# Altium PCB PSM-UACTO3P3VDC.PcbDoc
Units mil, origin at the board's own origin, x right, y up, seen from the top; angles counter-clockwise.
Board outline 8000 x 5800 mil, 2 copper layers (Top Layer, Bottom Layer), stack 62 mil thick; 68 components, 35 nets, 165 pads, 15 vias.
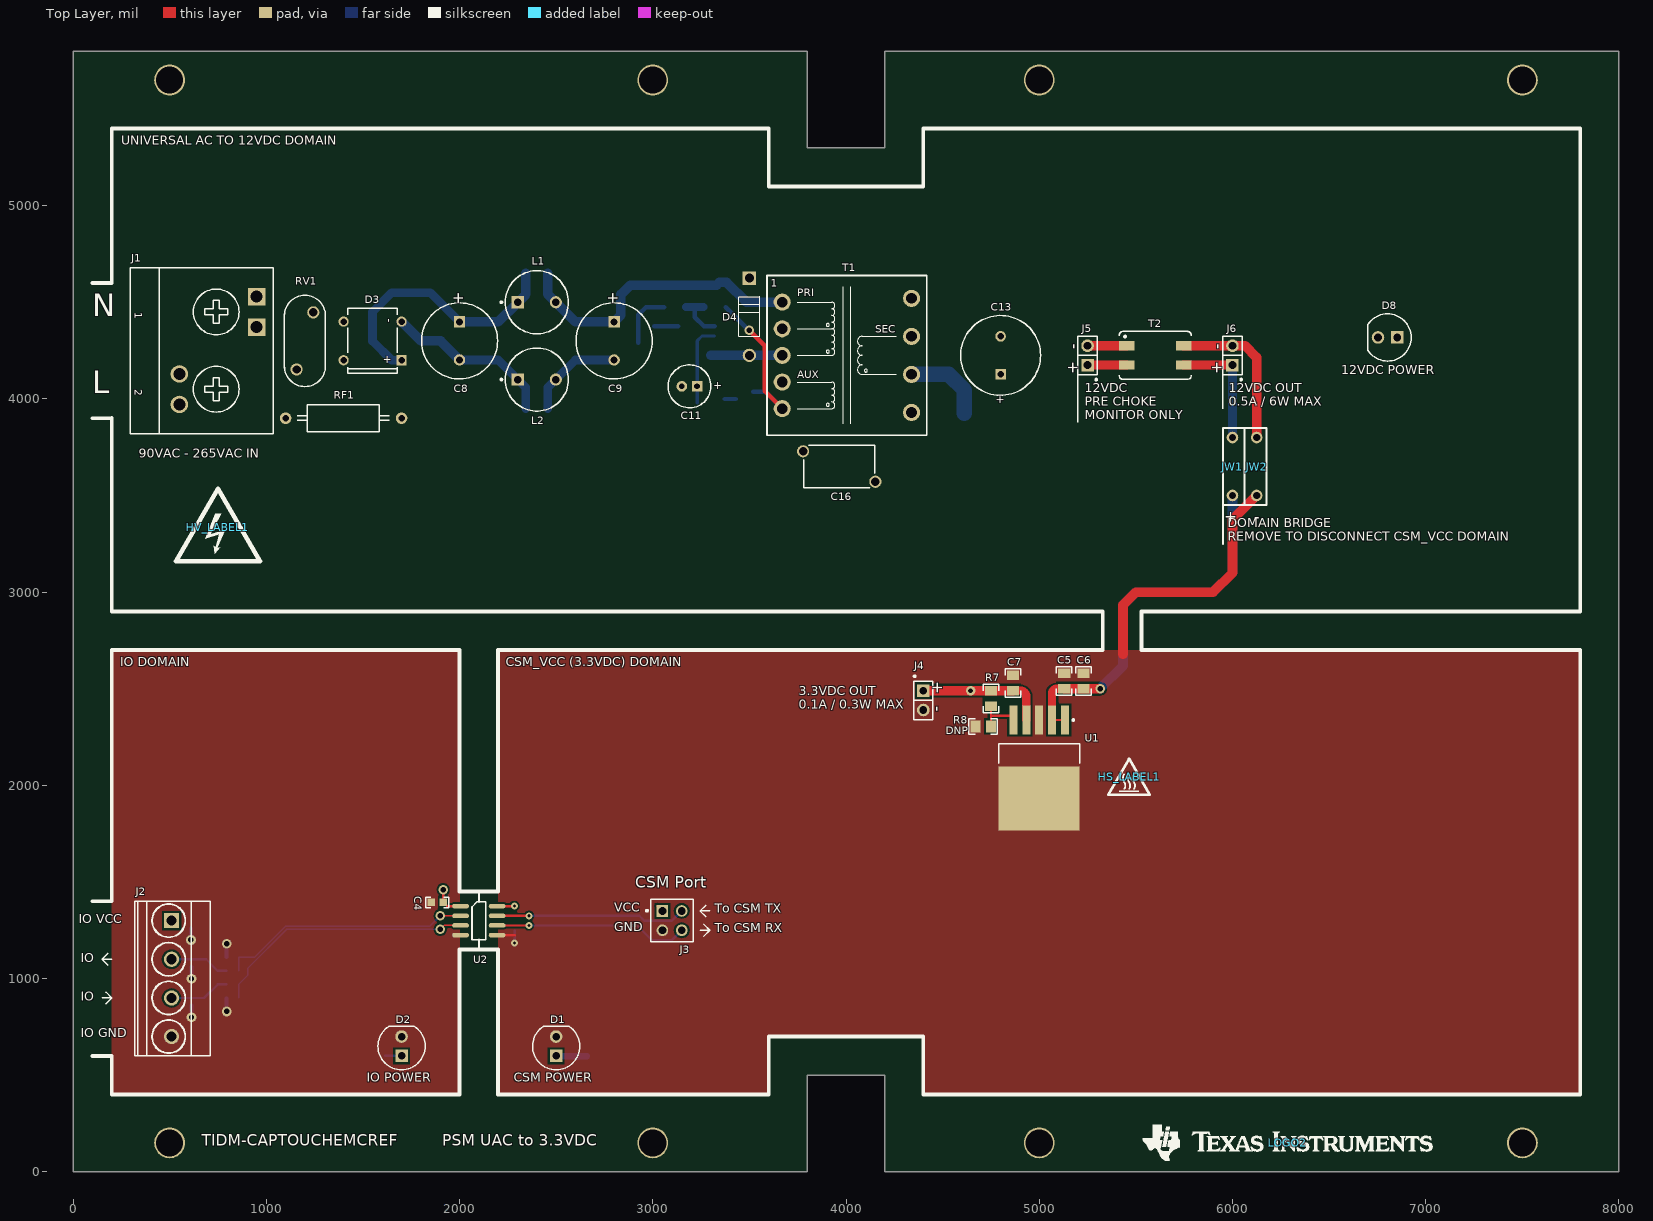
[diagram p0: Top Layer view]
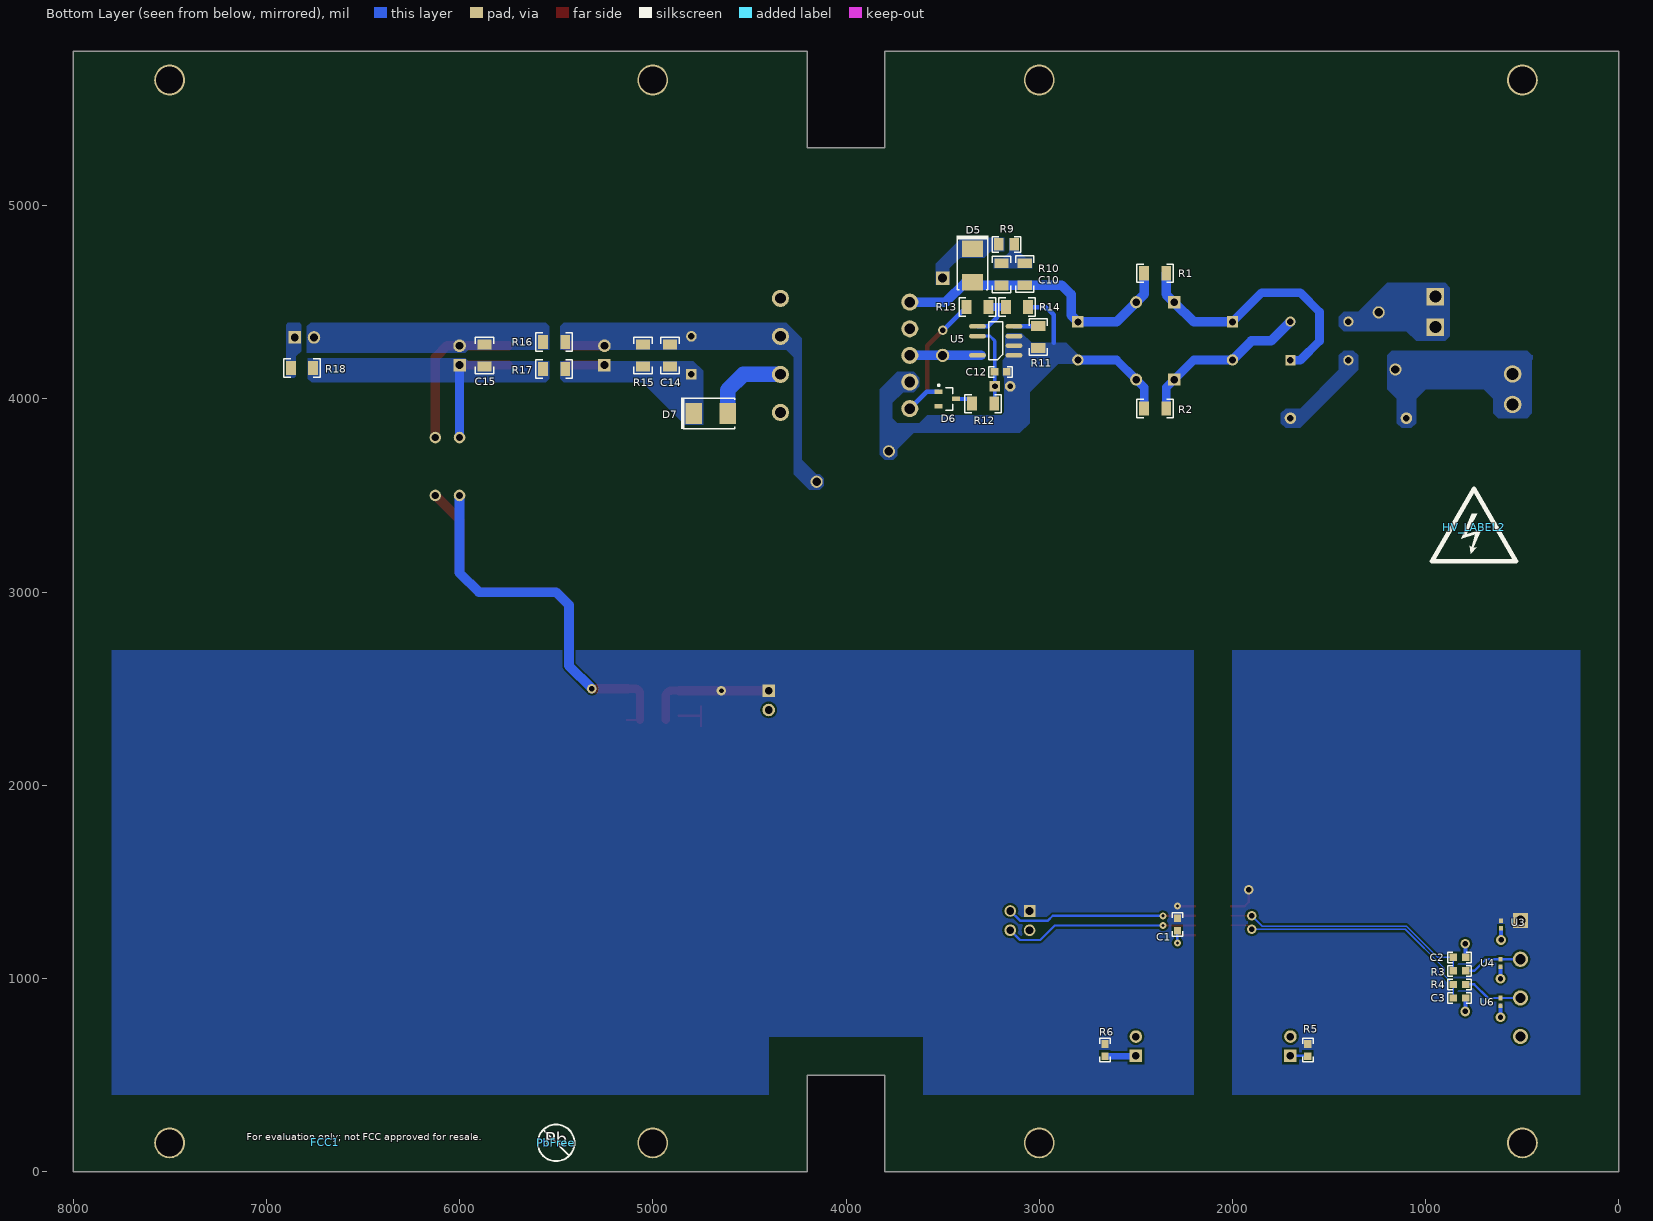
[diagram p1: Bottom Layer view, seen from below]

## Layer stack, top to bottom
Top Solder: solder mask 0.4, Solder Resist, Dk 3.5
Top Layer: signal copper 1.4
Dielectric1: core 59.2, FR-4, Dk 4.8
Bottom Layer: signal copper 1.4
Bottom Solder: solder mask 0.4, Solder Resist, Dk 3.5

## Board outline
0,0 0,5800 3800,5800 3800,5300 4200,5300 4200,5800 8000,5800 8000,0 4200,0 4200,500 3800,500 3800,0

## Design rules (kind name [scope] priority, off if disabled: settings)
AcuteAngle [All] p1: minimum=4.50000000000000E+0001 checktracksonly=FALSE
AssemblyTestPointUsage [All] p1: valid=2
Clearance Clearance_Keepouts [((IsTrack Or IsArc) And Not InPoly) And IsFree and IsKeepOut vs ((IsTrack Or IsArc) And Not InPoly) And IsFree and IsKeepOut] p1: gap=0
Clearance Clearance_BoardEdge_MountingHoles [OnCopper and InComponentClass('Mounting Holes') vs IsKeepOut] p2: gap=40
Clearance Clearance_BoardEdge_Poly [OnCopper and InPoly vs IsKeepOut] p3: gap=25
Clearance Clearance_BoardEdge [OnCopper and Not InComponentClass('Logo') and not InComponentClass('FiducialMark') and not InRegion(1000,500,4000,800) and Not IsKeepout vs IsKeepOut] p4: gap=75
Clearance Clearance_Poly [InPolygon] p5: gap=10
Clearance [All] p6: gap=7.87
ComponentClearance ComponentClearance_MountingHoles_FiducialMarks [InComponentClass('Mounting Holes') vs InComponentClass('FiducialMark')] p1: gap=50 collisioncheckmode=3 verticalgap=10 showdistances=FALSE
ComponentClearance ComponentClearance_Shunt [InComponentClass('Header') vs InComponentClass('Shunt')] p2: gap=0 collisioncheckmode=3 verticalgap=0 showdistances=FALSE
ComponentClearance ComponentClearance_Logo [InComponentClass('Logo')] p3: gap=50 collisioncheckmode=3 verticalgap=10 showdistances=FALSE
ComponentClearance ComponentClearance_ScrewToNut [(HasFootprint('NY PMS 440 0025 PH')) vs (HasFootprint('Keystone_1902C'))] p4: gap=5 collisioncheckmode=3 verticalgap=10 showdistances=FALSE
ComponentClearance ComponentClearance_MountingHoles [InComponentClass('Mounting Holes')] p5: gap=250 collisioncheckmode=3 verticalgap=100000 showdistances=FALSE
ComponentClearance ComponentClearance_SmallPassives [HasFootprint('0201*') or HasFootprint('0402*') or HasFootprint('0508') or HasFootprint('0603*') or HasFootprint('0612') or HasFootprint('0805*') or HasFootprint('0815*') or HasFootprint('0830*') or HasFootprint('1206*') or HasFootprint('1210*') or HasFootprint('1808*') or HasFootprint('1812*') or HasFootprint('1825*') or HasFootprint('2010*') or HasFootprint('2220*') or HasFootprint('2225*') or HasFootprint('2512*') or HasFootprint('2728*') or HasFootprint('3518*') vs HasFootprint('0201*') or HasFootprint('0402*') or HasFootprint('0508') or HasFootprint('0603*') or HasFootprint('0612') or HasFootprint('0805*') or HasFootprint('0815*') or HasFootprint('0830*') or HasFootprint('1206*') or HasFootprint('1210*') or HasFootprint('1808*') or HasFootprint('1812*') or HasFootprint('1825*') or HasFootprint('2010*') or HasFootprint('2220*') or HasFootprint('2225*') or HasFootprint('2512*') or HasFootprint('2728*') or HasFootprint('3518*')] p6: gap=20 collisioncheckmode=3 verticalgap=10 showdistances=FALSE
ComponentClearance ComponentClearance_THtoSMT [IsThruComponent vs IsSMTComponent] p7: gap=25 collisioncheckmode=3 verticalgap=30 showdistances=FALSE
ComponentClearance ComponentClearance_THtoTH [IsThruComponent vs IsThruComponent] p8: gap=50 collisioncheckmode=3 verticalgap=30 showdistances=FALSE
ComponentClearance [All] p9: gap=40 collisioncheckmode=3 verticalgap=10 showdistances=FALSE
DiffPairsRouting [All] p1: maxlimit=100 minlimit=10 mostfreqgap=10 toplayer_minwidth=15 toplayer_maxwidth=15 toplayer_prefwidth=15 bottomlayer_minwidth=15 bottomlayer_maxwidth=15 bottomlayer_prefwidth=15 maxuncoupledlength=1000
FabricationTestPointUsage TestPointUsage [All] p1: valid=2 allowmultiple=FALSE
FabricationTestpoint Testpoint [All] p1: side=3 testpointundercomponent=TRUE minsize=40 maxsize=100 preferedsize=60 minholesize=0 maxholesize=40 preferedholesize=32 testpointgrid=1 allowsidetop=TRUE allowsidebottom=TRUE usegrid=TRUE gridtolerance=0.01
FanoutControl Fanout_LCC [IsLCC] p1: bgadir=Out bgaviamode=Centered fanoutstyle=Auto fanoutdirection=Alternating viagrid=1 // Fanout_LCC (Default Rule)
FanoutControl Fanout_BGA [IsBGA] p2: bgadir=Out bgaviamode=Centered fanoutstyle=Auto fanoutdirection=Alternating viagrid=1 // Fanout_BGA (Default Rule)
FanoutControl Fanout_Default [All] p4: bgadir=Out bgaviamode=Centered fanoutstyle=Auto fanoutdirection=Alternating viagrid=1 // Fanout_Default (Default Rule)
FanoutControl Fanout_Small [(CompPinCount < 5)] p5: bgadir=Out bgaviamode=Centered fanoutstyle=Auto fanoutdirection=OutThenIn viagrid=1 // Fanout_Small (Default Rule)
Height [All] p1: minheight=0 maxheight=1500 prefheight=500
HoleSize [All] p1: absolutevalues=TRUE maxlimit=251 minlimit=8 maxpercent=80.000 minpercent=20.000
MinimumAnnularRing MinimumAnnularRing_ThermalPadVias [IsVia and InAnyComponent] p1: minimumring=5.91
MinimumAnnularRing [All] p2: minimumring=8
MinimumSolderMaskSliver MinimumSolderMaskSliver_Logo [InComponentClass('Logo') vs InComponentClass('Logo')] p1: minsoldermaskwidth=0.7
MinimumSolderMaskSliver [All] p2: minsoldermaskwidth=3.94
PlaneConnect [All] p1: planeconnectstyle=Relief reliefexpansion=10 reliefentries=4 reliefconductorwidth=10 reliefairgap=10
PolygonConnect [All] p1: connectstyle=Direct reliefconductorwidth=10 reliefentries=4 polygonreliefangle="90 Angle" airgapwidth=10
RoutingVias ThermalPadVias [IsVia and InAnyComponent] p1: holewidth=7.87 width=19.68 viastyle="Through Hole" minholewidth=7.87 minwidth=19.68 maxholewidth=12.99 maxwidth=23.62
RoutingVias [All] p2: holewidth=16 width=34 viastyle="Through Hole" minholewidth=7.87 minwidth=26 maxholewidth=40 maxwidth=65
SilkToBoardRegionClearance [Not ((IsComment or IsDesignator) And (Hide <> 'False')) and not InRegion(1000,500,4000,800)] p1:
SilkToSilkClearance SilkToSilkClearance_Pb-FreeLogo [(HasFootprint('Pb-Free_Overlay_Medium') OR HasFootprint('Pb-Free_Overlay_Small')) vs (HasFootprint('Pb-Free_Overlay_Medium') OR HasFootprint('Pb-Free_Overlay_Small'))] p1: silktosilkclearance=0
SilkToSilkClearance [All] p2: silktosilkclearance=5
SilkToSolderMaskClearance "Silk to Solder Mask Opening" [All] p1: minsilkscreentomaskgap=1 clearancetoexposedcopper=FALSE
SolderMaskExpansion [All] p1: expansion=3
Width [All] p1: maxlimit=100 minlimit=6 preferedwidth=10 checkconnectedcopper=TRUE
14 further rules are at their usual default settings.

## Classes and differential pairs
component class Header: J3 J4 J5 J6
component class Logo: LOGO2

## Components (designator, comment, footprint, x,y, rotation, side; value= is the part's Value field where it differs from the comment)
C1 "GRM188R71C104KA01D" 0603 2285,1280 r270 bottom
C2 "06031C102JAT2A" 0603 825,1110 r180 bottom
C3 "06031C102JAT2A" 0603 825,900 r180 bottom
C4 "GRM188R71C104KA01D" 0603 1885,1395 r180 top
C5 "C2012X5R1E106K125AB" 0805_HV 5129,2540 r90 top
C6 "08053C104KAT2A" 0805_HV 5229,2540 r90 top
C7 "C2012X5R1C226K125AC" 0805_HV 4864,2530 r90 top
C8 "UCA2G6R8MPD1TD" CAPPR5-10x16 2000,4300 r270 top
C9 "EEUED2G100" CAPPR5-10X20 2800,4300 r270 top
C10 "C3216C0G2J222J" 1206 3195.32,4644.69 r90 bottom
C11 "ECA-1VM220" M_500x1100 3190,4065 r180 top
C12 "06033D104KAT2A" 0603 3200,4140 r180 bottom
C13 "16ZLJ1500M10X20" ZLJ_1000X2000 4800,4225 r90 top
C14 "C3216X7R1C106M" 1206 4910,4225 r90 bottom
C15 "C3216X7R1C105K/0.85" 1206 5870,4225 r90 bottom
C16 "440LD10-R" 440L_930x1250 3965,3650 r0 top
D1 "HLMP-3519" HLMP-351_GREEN 2500,650 r90 top
D2 "HLMP-3519" HLMP-351_GREEN 1700,650 r90 top
D3 "DF06M" DIOB_DFM 1550,4300 r180 top
D4 "1N4937-E3" DO-41 3500,4425 r270 top
D5 "SM6T150A" SMB 3345,4690 r270 bottom
D6 "BAS21" INF-SOT23_N 3475,3999.69 r180 bottom
D7 "MBRS1100T3G" SMB 4700,3925 r180 bottom
D8 "HLMP-3519" HLMP-351_GREEN 6803.15,4317.91 r180 top
FCC1 "FCC disclaimer" FCC_disclaimer 6694.5,153.5 r180 bottom
HS_LABEL1 "CAUTION HOT SURFACE" IEC_HotSurface_Small 5465,2045 r0 top
HV_LABEL1 "DANGER HIGH VOLTAGE" IEC_HighVoltage_Medium 750,3335 r0 top
HV_LABEL2 "DANGER HIGH VOLTAGE" IEC_HighVoltage_Medium 750,3335 r180 bottom
J1 "0399100102" CONN_399100102 750,4250 r270 top
J2 "39544-3004" MOLEX_39544-3004 510,1000 r270 top
J3 "PEC02DAAN" Sullins_PEC02DAAN 3100,1300 r0 top
J4 "HTSW-102-07-G-S" Samtec_HTSW-102-07-G-S 4400,2440 r270 top
J5 "HTSW-102-07-G-S" Samtec_HTSW-102-07-G-S 5250,4225 r90 top
J6 "HTSW-102-07-G-S" Samtec_HTSW-102-07-G-S 6000,4225 r90 top
JW1 "923345-03-C" 923345-03-C 6000,3650 r270 top
JW2 "923345-03-C" 923345-03-C 6125,3650 r90 top
L1 "768772102" IND_WE-TI_8095 2400,4500 r0 top
L2 "768772102" IND_WE-TI_8095 2400,4100 r0 top
LOGO2 "Texas Instruments" TI_Horizontal_Overlay_Medium 6285,150 r0 top
PbFree "Pb-Free Symbol" Pb-Free_Overlay_Medium 5500,150 r180 bottom
R1 "CRCW12066K80JNEA" 1206 2400,4650 r0 bottom
R2 "CRCW12066K80JNEA" 1206 2400,3950 r0 bottom
R3 "CRCW060351R0JNEA" 0603 825,1040 r0 bottom
R4 "CRCW060351R0JNEA" 0603 825,970 r0 bottom
R5 "CRCW0603120RJNEA" 0603 1610,630 r90 bottom
R6 "CRCW0603120RJNEA" 0603 2660,630 r90 bottom
R7 "CRCW08050000Z0EA" 0805_HV 4750,2450 r90 top
R8 "CRCW08050000Z0EA" 0805_HV 4710,2305 r0 top
R9 "CRCW080551R0JNEA" 0805_HV 3170,4800 r180 bottom
R10 "CRCW1206120KJNEA" 1206 3075,4645 r270 bottom
R11 "CRCW12061K65FKEA" 1206 3005,4320 r90 bottom
R12 "ERJ-8ENF33R0V" 1206 3290,3975 r0 bottom
R13 "CRCW1206100KFKEA" 1206 3320,4475 r180 bottom
R14 "CRCW120628K7FKEA" 1206 3115,4475 r0 bottom
R15 "RC1206FR-0739KL" 1206 5050,4225 r270 bottom
R16 "CRCW12060000Z0EA" 1206 5510,4155 r0 bottom
R17 "CRCW12060000Z0EA" 1206 5510,4295 r0 bottom
R18 "CRCW12061K00JNEA" 1206 6814.96,4160.43 r180 bottom
RF1 "FKN1WSJR-52-4R7" RESAD1524W55L900D150 1400,3900 r180 top
RV1 "S10K275E2" VAR_S10K275E2 1200,4300 r90 top
T1 "7508110325" 7508110325 3670,4225 r0 top
T2 "SRF0905-472Y" SRF0905 5600,4225 r0 top
U1 "TPS7A4533KTTR" KTT0005A_N 5000,2090 r270 top
U2 "ISO7221CD" D0008A_N 2100,1300 r0 top
U3 "TPD1E10B06DPYR" DPY0002A 610,1280 r90 bottom
U4 "TPD1E10B06DPYR" DPY0002A 612.76,1080 r90 bottom
U5 "UCC28910DR" D0007A_N 3225,4300 r0 bottom
U6 "TPD1E10B06DPYR" DPY0002A 612.76,880 r90 bottom

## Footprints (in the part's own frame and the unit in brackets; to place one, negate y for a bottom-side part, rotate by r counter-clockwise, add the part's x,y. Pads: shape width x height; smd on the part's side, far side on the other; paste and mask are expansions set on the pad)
440L_930x1250 [mm] "Vishay"
  round 1.6 hole 1.092: 1(-4.75,2) 2(4.75,-2)
  silkscreen extent -4.65,-2.8 4.65,2.8, body extent -5.25,-2.8 5.25,2.8, height 12.46
0603 [mm] "0603 from SM-752 data"
  rect 1x0.95 smd: 1(-0.8,0) 2(0.8,0)
  silkscreen extent -1.52,-0.69 1.52,0.69, body extent -0.87,-0.47 0.87,0.47, height 0.85
0805_HV [mil] "0805 with 30mil clearance between pads"
  rect 50x63 smd: 1(-40,0) 2(40,0)
  silkscreen extent -74,-40 74,40, body extent -43,-29 43,29, height 43
1206 [mm] "1206 from SM-752 data"
  rect 1.3x1.85 smd: 1(-1.45,0) 2(1.45,0)
  silkscreen extent -2.4,-1.21 2.4,1.21, body extent -1.7,-0.9 1.7,0.9, height 1.35
923345-03-C [mil] "Wire Jumper"
  round 60 hole 38: 1(-150,0) 2(150,0)
  body extent -163,-40 163,37, height 100
7508110325 [mm] "Flyback Transformer True Position Grid"
  round 2.25 hole 1.4: 1(0,7) 2(0,3.5) 3(0,0) 4(0,-3.5) 5(0,-7) 6(17,-7.5) 7(17,-2.5) 8(17,2.5) 9(17,7.5)
  silkscreen extent -2,-10.5 19,10.5
CAPPR5-10x16 [mm] "Capacitor, Electrolytic, Radial; Body 10 x 16 mm (Dia.xH typ); Pin Spacing 5 mm (typ)"
  rect 1.5x1.5 hole 0.9: 1(-2.5,0)
  round 1.5 hole 0.9: 2(2.5,0)
  silkscreen extent -5,-5 5,5, body extent -5.03,-5.03 5.03,5.02, height 16.29
CAPPR5-10X20 [mm] "Capacitor, Electrolytic, Radial; Body 10 x 20 mm (Dia.xH typ); Pin Spacing 5 mm (typ)"
  rect 1.5x1.5 hole 0.9: 1(-2.5,0)
  round 1.5 hole 0.9: 2(2.5,0)
  silkscreen extent -5,-5 5,5, body extent -5,-5 5,5, height 22
CONN_399100102 [mm] "Molex"
  rect 2.3x2.3 hole 1.587: 1(-7.085,5.08) 1A(-3.075,5.08)
  round 2.3 hole 1.587: 2(3.075,-5.08) 2A(7.085,-5.08)
  silkscreen extent -10.88,-11.53 10.96,7.27, body extent -10.88,-11.53 10.96,7.27, height 31.1
D0007A_N [mm] "SOIC, 7-Leads, Body 4.9x3.9mm, Pitch 1.27mm, IPC Medium Density"
  oval 2.2x0.6 smd: 1(-2.4,1.905) 2(-2.4,0.635) 3(-2.4,-0.635) 4(-2.4,-1.905) 5(2.4,-1.905) 6(2.4,-0.635) 8(2.4,1.905)
  silkscreen extent -0.9,-2.5 0.9,2.5, body extent -3,-2.5 3,2.5, height 1.54
D0008A_N [mm] "SOIC, 8-Leads, Body 4.9x3.9mm, Pitch 1.27mm, IPC Medium Density"
  oval 2.2x0.6 smd: 1(-2.4,1.905) 2(-2.4,0.635) 3(-2.4,-0.635) 4(-2.4,-1.905) 5(2.4,-1.905) 6(2.4,-0.635) 7(2.4,0.635) 8(2.4,1.905)
  silkscreen extent -0.9,-2.5 0.9,2.5, body extent -3,-2.45 3,2.45, height 1.63
DIOB_DFM [mm] "Diodes Inc DFM package"
  rect 1.35x1.35 hole 0.85: 1(-3.81,2.54)
  round 1.35 hole 0.85: 2(-3.81,-2.54) 3(3.81,-2.54) 4(3.81,2.54)
  silkscreen extent -3.25,-4.27 3.25,4.24, body extent -3.93,-4.25 3.93,4.26, height 4.68
DO-41 [mm] "diode"
  rect 1.75x1.75 hole 1.15: 1(-5.08,0)
  round 1.75 hole 1.15: 2(5.08,0)
  silkscreen extent -2.62,-1.37 2.59,1.35, body extent -5.51,-1.36 5.51,1.36, height 2.72
DPY0002A [mm] "R-PX2SON-N2"
  rect 0.6x0.5 smd: 1(-0.5,0) 2(0.5,0)
  body extent -0.55,-0.35 0.55,0.35, height 0.4
FCC_disclaimer [mil]
HLMP-351_GREEN [mm] "AVAGO"
  rect 1.65x1.65 hole 1: 1(-1.27,0)
  round 1.65 hole 1: 2(1.27,0)
  silkscreen extent -3.1,-3.1 2.6,3.1, body extent -3.05,-3.06 2.57,3.06, height 10.78
IEC_HighVoltage_Medium [mil]
  silkscreen extent -217,-176 217,200
IEC_HotSurface_Small [mil]
  silkscreen extent -107,-93 107,92
IND_WE-TI_8095 [mm] "Wurth WE-TI 8095"
  rect 1.6x1.6 hole 1: 1(-2.5,0)
  round 1.6 hole 1: 2(2.5,0)
  silkscreen extent -4.79,-4.15 4.15,4.15, body extent -4.12,-4.14 4.15,4.14, height 10
INF-SOT23_N [mm] "SOT23, 3-Leads, Body 2.9x1.3 mm, Pitch 0.95 mm, IPC Medium Density"
  rect 1.05x0.6 smd: 1(-1.15,0.95) 2(-1.15,-0.95) 3(1.15,0)
  silkscreen extent -1.28,-1.5 0.7,1.92, body extent -0.7,-1.5 0.7,1.5, height 1.1
KTT0005A_N [mm] "D2-PAK, 6-Leads, Body 8.9x10.2mm, Pitch 1.7mm, Lead Span 15.2mm, IPC Medium Density"
  rect 3.8x1.05 smd: 1(-6.3,3.4) 2(-6.3,1.7) 3(-6.3,0) 4(-6.3,-1.7) 5(-6.3,-3.4)
  rect 8.4x10.65 smd: 6(4,0)
  silkscreen extent -6.42,-5.35 -0.65,5.35, body extent -3.2,-5.32 6.45,5.33, height 4.83
M_500x1100 [mm] "PANASONIC"
  rect 1.4x1.4 hole 0.75: 1(-1,0)
  round 1.4 hole 0.75: 2(1,0)
  silkscreen extent -2.82,-2.82 2.81,2.82, body extent -2.73,-2.75 2.75,2.75, height 12.01
MOLEX_39544-3004 [mm] "Molex"
  rect 2x2 hole 1.321: 1(-7.62,0)
  round 2 hole 1.321: 2(-2.54,0) 3(2.54,0) 4(7.62,0)
  silkscreen extent -10.16,-4.83 10.16,5.08, body extent -10.16,-4.83 10.16,5.08, height 14.49
Pb-Free_Overlay_Medium [mil]
  silkscreen extent -95,-95 95,95
RESAD1524W55L900D150 [mil]
  round 60 hole 33.46: 1(-300,0) 2(300,0)
  silkscreen extent -236,-71 240,71, body extent -312,-71 312,71, height 141
Samtec_HTSW-102-07-G-S [mm] "Samtec 100mil, 1x2, 230 mil above insulator"
  rect 1.65x1.65 hole 1.016 mask+0: 1(-1.27,0)
  round 1.65 hole 1.016 mask+0: 2(1.27,0)
  silkscreen extent -3.3,-1.27 2.54,1.27, body extent -2.54,-1.27 2.54,1.27, height 8.38
SMB [mil] "Molded Diode, 2-Leads, Body 5.4x3.6mm, IPC Medium Density, based on OnSemi component dimensions"
  rect 85x107.99 smd: 1(-87.01,0) 2(87.01,0)
  silkscreen extent -155,-82 125,82, body extent -106,-71 106,71, height 91
SRF0905 [mm] "Bourns SRF0905 series recommended land pattern"
  rect 2x1.2 smd: 1(-3.75,1.27) 2(-3.75,-1.27) 3(3.75,-1.27) 4(3.75,1.27)
  silkscreen extent -4.75,-3.15 4.75,3.15, body extent -4.75,-3.15 4.75,3.15, height 5.3
Sullins_PEC02DAAN [mil] "Sullins Connector Solutions"
  rect 60x60 hole 40: 1(-50,50)
  round 60 hole 40: 2(50,50) 3(-50,-50) 4(50,-50)
  silkscreen extent -134,-110 110,110, body extent -110,-110 110,110, height 310
TI_Horizontal_Overlay_Medium [mil]
  silkscreen extent -750,-94 750,94
VAR_S10K275E2 [mm] "EPCOS"
  round 1.6 hole 1.1: 1(-3.75,1.1) 2(3.75,-1.1)
  silkscreen extent -6,-2.7 6,2.7, body extent -5.98,-2.7 5.98,2.7, height 14.99
ZLJ_1000X2000 [mm] "Rubycon"
  rect 1.4x1.4 hole 0.838: 1(-2.5,0)
  round 1.4 hole 0.838: 2(2.5,0)
  silkscreen extent -5.25,-5.25 5.25,5.25, body extent -5.21,-5.24 5.24,5.24, height 22.01

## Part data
C1 C4: "CAP, CERM, 0.1 µF, 16 V, +/- 10%, X7R, 0603"
C2 C3: "CAP, CERM, 1000 pF, 100 V, +/- 5%, X7R, 0603"
C5: "CAP, CERM, 10 µF, 25 V, +/- 10%, X5R, 0805"
C6: "CAP, CERM, 0.1 µF, 25 V, +/- 10%, X7R, 0805"
C7: "CAP, CERM, 22 µF, 16 V, +/- 10%, X5R, 0805"
C8: "CAP, AL, 6.8 µF, 400 V, +/- 20%, TH"
C9: "CAP, AL, 10 µF, 400 V, +/- 20%, 2.864788 ohm, TH"
C10: "CAP, CERM, 2200 pF, 630 V, +/- 5%, C0G/NP0, 1206"
C11: "CAP, AL, 22 µF, 35 V, +/- 20%, TH"
C12: "CAP, CERM, 0.1 µF, 25 V, +/- 10%, X5R, 0603"
C13: "CAP, AL, 1500 µF, 16 V, +/- 20%, 0.028 ohm, TH"
C14: "CAP, CERM, 10 µF, 16 V, +/- 20%, X7R, 1206"
C15: "CAP, CERM, 1 µF, 16 V, +/- 10%, X7R, 1206"
C16: "CAP, CERM, 1000 pF, 400 V, +/- 20%, Y5U, Disc, 9.3x12.5mm"
D1 D2 D8: "LED, Green, TH"
D3: "Diode, Switching-Bridge, 600 V, 1 A, TH"
D4: "Diode, Switching, 600 V, 1 A, TH"
D5: "Diode, TVS, Uni, 128 V, 600 W, SMB"
D6: "Silicon Switching Diode, SOT23, Reel, Green"
D7: "Diode, Schottky, 100 V, 1 A, SMB"
FCC1: library part FCC_disclaimer, "FCC_disclaimer"
HS_LABEL1: library part IEC_HotSurface, "IEC 61010-1 Hot Surface Warning"
HV_LABEL1 HV_LABEL2: library part IEC_HighVoltage, "IEC 61010-1 High Voltage Warning"
J1: "Terminal Block, 60A, 10.16mm Pitch, 2-Pos, TH"
J2: "Terminal Block, 4x1, 5.08mm, TH"
J3: "Header, 100mil, 2x2, Tin, TH"
J4 J5 J6: "Header, 100mil, 2x1, Gold, TH"
JW1 JW2: "Jumper Wire, 300mil spacing, Orange, pkg of 200"
L1 L2: "Inductor, Shielded Drum Core, Metal Composite, 1 mH, 0.5 A, 1.7 ohm, TH"
LOGO2: library part TI_Logo, "Texas Instrument Corporate Signature"
PbFree: library part Pb-Free
R1 R2: "RES, 6.8 k, 5%, 0.25 W, 1206"
R3 R4: "RES, 51, 5%, 0.1 W, 0603"
R5 R6: "RES, 120, 5%, 0.1 W, 0603"
R7 R8: "RES, 0 ohm, 5%, 0.125W, 0805"
R9: "RES, 51, 5%, 0.125 W, 0805"
R10: "RES, 120 k, 5%, 0.25 W, 1206"
R11: "RES, 1.65 k, 1%, 0.25 W, 1206"
R12: "RES, 33.0, 1%, 0.25 W, 1206"
R13: "RES, 100 k, 1%, 0.25 W, 1206"
R14: "RES, 28.7 k, 1%, 0.25 W, 1206"
R15: "RES, 39.0 k, 1%, 0.25 W, 1206"
R16 R17: "RES, 0, 5%, 0.25 W, 1206"
R18: "RES, 1.0 k, 5%, 0.25 W, 1206"
RF1: "RES, 4.7, 5%, 1 W, Fusible, TH"
RV1: "Varistor 275V RMS 10MM Radial, TH"
T1: "Flyback Transformer, 90-375V @ 100kHz (PRI), 12V/500mA (SEC), 18V/10mA (AUX)"
T2: "Line Filter"
U1: "Single Output Fast Transient Response LDO, 1.5 A, Fixed 3.3 V Output, 2.1 to 20 V Input, 5-pin DDPAK (KTT), -40 to 125 degC, Green (RoHS & no Sb/Br)"
U2: "25 Mbps Dual Channels, 1 / 1, Digital Isolator, 3.3 V / 5 V, -40 to +125 degC, 8-pin SOIC (D), Green (RoHS & no Sb/Br)"
U3 U4 U6: "ESD in 0402 Package with 10 pF Capacitance and 6 V Breakdown, 1 Channel, -40 to +125 degC, 2-pin X2SON (DPY), Green (RoHS & no Sb/Br)"
U5: "High-Voltage Flyback Switcher with Primary-Side Regulation and Constant-Current Control, D0007A"

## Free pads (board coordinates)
  round 160 hole 140: 0(500,150) 0(500,5650) 0(3000,150) 0(3000,5650) 0(5000,150) 0(5000,5650) 0(7500,150) 0(7500,5650)

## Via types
v1: diameter 50, hole 28, Top Layer to Bottom Layer, 10 vias
v2: diameter 36, hole 16, Top Layer to Bottom Layer, 4 vias
v3: diameter 50, hole 25, Top Layer to Bottom Layer, 1 vias

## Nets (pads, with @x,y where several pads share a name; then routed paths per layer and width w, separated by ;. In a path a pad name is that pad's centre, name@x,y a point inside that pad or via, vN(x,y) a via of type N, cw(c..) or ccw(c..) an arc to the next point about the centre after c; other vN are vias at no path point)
AUX+: D6.1 R13.1 T1.5 | length 834.7
  Top Layer w22: 3580,4039.41 T1.5
  Top Layer w24: v1(3500,4355) 3580,4275 3580,4039.41
  Bottom Layer w24: R13.1 3497.09,4355 v1(3500,4355) ; D6.1 3582.32,4037.09 T1.5
CSM_RXD: J3.4 U2.6 | length 1007.3
  Top Layer w12: U2.6 v2(2360,1275)
  Bottom Layer w12: v2(2360,1275) 2920,1275 2995,1200 3100,1200 J3.4
CSM_TXD: J3.2 U2.7 | length 986.6
  Top Layer w12: U2.7 v2(2360,1325)
  Bottom Layer w12: v2(2360,1325) 2930,1325 2955,1300 3100,1300 J3.2
CSM_VCC: C1.1 C7.1 J3.1 J4.1 R6.2 R7.2 U1.4 U2.8 | length 796.9
  Top Layer w12: U2.8 v2(2283.5,1375) ; J3.1@3025,1375 J3.1
  Top Layer w42: C7.1 4904,2490 cw(c4904,2460.93) 4933.07,2460.93 U1.4
  Top Layer w50: J4.1 v3(4645,2490) R7.2 C7.1
GND: C1.2 C5.2 C6.2 C7.2 D1.2 J3.3 J4.2 JW2.1 R8.1 U1.3 U1.6 U2.5 | length 1495.4
  Top Layer w12: U2.5@2195.98,1225 2285,1225
  Top Layer w50: 5433.07,2678.07 5433.07,2933.07 5500,3000 5900,3000 6000,3100 6000,3375 JW2.1
  Bottom Layer w12: v2(2285,1185) C1.2
GND_PRECHOKE: C13.2 C14.2 C16.2 J5.2 R15.1 R17.1 T1.8 T2.1 | length 202.4
  Top Layer w47: J5.2 T2.1
IO_GND: C2.2 C3.2 C4.2 D2.2 J2.4 U2.4 U3.1 U4.1 U6.1 | length 318
  Bottom Layer w20: v1(610,1200) U3.1 ; v1(612.76,800) U6.1 ; v1(612.76,1000) U4.1 ; v1(795,830) C3.2@795,898.5 ; C2.2@795,1111.5 v1(795,1180)
IO_RXD: J2.3 R4.1 U6.2 | length 312.3
  Bottom Layer w12: J2.3 U6.2@612.45,900 ; U6.2 678.19,899.68 748.5,970 R4.1
IO_TXD: J2.2 R3.1 U4.2 | length 308.5
  Bottom Layer w12: J2.2 612.76,1100 U4.2 688.82,1099.68 748.5,1040 R3.1
IO_VCC: C4.1 J2.1 R5.2 U2.1 U3.2 | length 160.8
  Top Layer w12: v1@1916.5,1458.5 C4.1 1936.5,1375 U2.1
  other v1: 1915,1460
LINE: D3.4 RF1.1
NetC2_1: C2.1 R3.2 U2.2 | length 1314.3
  Top Layer w8: v1@1900,1340 1915,1325 U2.2
  Bottom Layer w8: R3.2 C2.1 938.43,1110 1099.3,1270.87 1845.87,1270.87 v1(1900,1325)
NetC3_1: C3.1 R4.2 U2.3 | length 1366.2
  Top Layer w8: v1(1900,1255) 1920,1275 U2.3
  Bottom Layer w8: C3.1 R4.2 905,1018.5 905,1054.13 1105.87,1255 v1(1900,1255)
NetC8_1: C8.1 D3.1 L1.1 R1.1 | length 1406.4
  Bottom Layer w45: D3.1 1649.99,4200 1550,4299.99 1550,4450 1650,4550 1848.43,4550 C8.1
  Bottom Layer w50: C8.1 2200,4398.43 L1.1 2342.91,4541.34 R1.1
NetC8_2: C8.2 D3.2 L2.1 R2.1 | length 893
  Bottom Layer w45: C8.2 2200,4201.57 L2.1 2342.91,4058.66 R2.1
  Bottom Layer w50: D3.2 1800,4300 1901.57,4300 C8.2
NetC10_2: C10.2 R9.2 R10.1
NetC15_1: C15.1 J6.1 JW1.1 R16.2 R18.2 T2.3 | length 627.4
  Top Layer w47: T2.3 J6.1
  Bottom Layer w47: JW1.1 J6.1
NetC15_2: C15.2 D8.2 J6.2 JW2.2 R17.2 T2.4 | length 817.2
  Top Layer w47: T2.4 J6.2
  Top Layer w50: J6.2 6065,4275 6125,4215 JW2.2
NetD1_1: D1.1 R6.1 | length 161.5
  Bottom Layer w32: D1.1@2498.5,598.5 R6.1
NetD2_1: D2.1 R5.1 | length 84.3
  Bottom Layer w12: R5.1@1615.71,600 D2.1
NetD4_1: D4.1 D5.1 R9.1
NetD6_3: D6.3 R12.2 | length 57.6
  Bottom Layer w22: R12.2@3372.09,3999.69 D6.3
NetD7_2: D7.2 T1.7 | length 427.8
  Bottom Layer w80: T1.7 4531.89,4126.57 4612.99,4045.47 D7.2
NetD8_1: D8.1 R18.1
NetJ1_2: J1.2 J1.2A RF1.2 RV1.1
NetR7_1: R7.1 R8.2 U1.5 | length 220
  Top Layer w12: R8.2 4750,2360 ; R7.1 4750,2360 ; U1.5@4865,2360 4750,2360
NetR11_2: R11.2 U5.4 | length 123.4
  Bottom Layer w24: R11.2@3007.09,4375 U5.4
NEUTRAL: D3.3 J1.1 J1.1A RV1.2
PRIMARY+: D4.2 T1.3 U5.8 | length 370
  Bottom Layer w50: U5.8@3300,4225 D4.2 T1.3
PWR_GND: C9.2 C11.2 C12.2 C16.1 L2.2 R2.2 R11.1 R14.1 T1.4 U5.1 U5.2 U5.3 | length 805.3
  Bottom Layer w24: 2925,4290 2925,4435 2965,4475 R14.1
  Bottom Layer w45: R2.2 2457.09,4058.66 L2.2 2600,4201.57 C9.2
PWR_HV: C9.1 C10.1 D5.2 L1.2 R1.2 R10.2 T1.1 | length 1549
  Bottom Layer w50: R1.2 2457.09,4541.34 L1.2 2600,4398.43 C9.1 2835,4433.43 2835,4540 2882.92,4587.92 R10.2 D5.2@3329.92,4587.92 ; D5.2 3382,4603 3484.41,4500.59 T1.1
PWR_VDD: C11.1 C12.1 R12.1 U5.6 | length 421.9
  Bottom Layer w16: R12.1@3230,3977.91 3230,4300 3255,4325 U5.6
PWR_VS: R13.2 R14.2 U5.5 | length 265
  Bottom Layer w24: 3217.5,4475 3217.5,4422.5 3265,4375 U5.5
  Bottom Layer w40: R14.2 3217.5,4475 R13.2
VCC_12: C5.1 C6.1 JW1.2 U1.1 U1.2 | length 1985.5
  Top Layer w12: U1.2 U1.1
  Top Layer w42: U1.2 5066.93,2477.93 cw(c5089,2477.93) 5089,2500 C5.1
  Top Layer w50: C5.1 C6.1 v1(5314.96,2500)
  Bottom Layer w50: v1(5314.96,2500) 5433.07,2618.11 5433.07,2933.07 5500,3000 5900,3000 6000,3100 JW1.2
VCC_12_PRECHOKE: C13.1 C14.1 D7.1 J5.1 R15.2 R16.1 T2.2 | length 202.4
  Top Layer w47: J5.1 T2.2
pads on no net: D6.2 T1.2 T1.6 T1.9

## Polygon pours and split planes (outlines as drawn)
IO_VCC on Bottom Layer "IO_VCC_L02_P044" (solid, remove dead copper, pour order 44): 200,2700 2000,2700 2000,400 200,400 200,2690
GND_PRECHOKE on Bottom Layer "Bottom Layer-No Net 9" (solid, remove dead copper, pour order 31): 4290,4375 4230,4315 4230,3750 4230,3685 4155,3610 4135,3610 4115,3590 4115,3550 4135,3530 4150,3530 4190,3530 4270,3610 4270,4215 4310,4255 4310,4395 4290,4375
PWR_GND on Bottom Layer "Bottom Layer-No Net 12" (solid, remove dead copper, pour order 29): 3620,3825 3650,3825 3735,3740 3735,3705 3755,3685 3800,3685 3825,3710 3825,3870 3810,3885 3775,3850 3645,3850 3620,3825
LINE on Bottom Layer "Bottom Layer-No Net 3" (solid, remove dead copper, pour order 32): 1375,4250 1350,4225 1350,4150 1650,3850 1725,3850 1750,3875 1750,3925 1725,3950 1650,3950 1450,4150 1450,4225 1425,4250 1375,4250 1350,4225
NEUTRAL on Bottom Layer "Bottom Layer-No Net 4" (solid, remove dead copper, pour order 30): 875,4575 900,4600 1200,4600 1350,4450 1425,4450 1450,4425 1450,4375 1425,4350 1100,4350 1050,4300 900,4300 875,4325 875,4575
NetJ1_2 on Bottom Layer "Bottom Layer-No Net 7" (solid, remove dead copper, pour order 24): 450,3925 475,3900 625,3900 650,3925 650,4000 700,4050 1000,4050 1050,4000 1050,3875 1075,3850 1125,3850 1150,3875 1150,4000 1200,4050 1200,4200 1200,4225 1175,4250 1150,4250 475,4250 450,4225 445.68,4225 445.68,4204.32 450,4200 450,3925
NetJ1_2 on Bottom Layer "Bottom Layer-No Net 6" (solid, remove dead copper, pour order 23): 450,3950 500,3900 600,3900 650,3950 650,4000 700,4050 1000,4050 1050,4000 1050,3900 1100,3850 1150,3900 1150,4000 1200,4050 1200,4200 1150,4250 500,4250 450,4200 450,3950
CSM_VCC on Bottom Layer "Bottom Layer-No Net 1" (solid, remove dead copper, pour order 21): 2200,2700 2200,400 3600,400 3600,700 4400,700 4400,400 7800,400 7800,2700 2200,2700
GND_PRECHOKE on Bottom Layer "Bottom Layer-No Net 14" (solid, remove dead copper, pour order 33): 4310,4255 4290,4275 4290,4375 4310,4395 4500,4395 5460,4395 5480,4375 5480,4255 4980,4255 4310,4255
NetD8_1 on Bottom Layer "Bottom Layer-No Net 17" (solid, remove dead copper, pour order 34): 6846.46,4117.13 6854.33,4109.25 6866.14,4109.25 6889.76,4109.25 6897.64,4117.13 6897.64,4380.91 6897.64,4384.84 6889.76,4392.72 6826.77,4392.72 6818.9,4384.84 6818.9,4247.05 6846.46,4219.49 6846.46,4117.13
NetC15_1 on Bottom Layer "Bottom Layer-No Net 13" (solid, remove dead copper, pour order 35): 5535,4195 5955,4195 5970,4210 6000,4210 6785,4210 6785,4125 6785,4105 6765,4085 5555,4085 5535,4105 5535,4195
NetC15_2 on Bottom Layer "Bottom Layer-No Net 16" (solid, remove dead copper, pour order 37): 5535,4255 5535,4375 5555,4395 6750,4395 6770,4395 6790,4375 6790,4360 6790,4240 5970,4240 5955,4255 5535,4255
VCC_12_PRECHOKE on Bottom Layer "Bottom Layer-No Net 15" (solid, remove dead copper, pour order 38): 5480,4195 5480,4105 5460,4085 5400,4085 5055,4085 4835,3865 4740,3865 4740,4145 4790,4195 4850,4195 5480,4195
NetC10_2 on Bottom Layer "Bottom Layer-No Net 5" (solid, remove dead copper, pour order 39): 3035,4675 3235,4675 3235,4730 3185,4730 3155,4760 3155,4765 3155,4828.55 3153.55,4830 3105,4830 3105,4765 3070,4730 3035,4730 3035,4675
PWR_GND on Bottom Layer "Bottom Layer-No Net 11" (solid, remove dead copper, pour order 40): 2800,4201.57 2800,4181.54 3046.54,4181.54 3070,4205 3165,4205 3175,4215 3175,4330 3165,4340 3090,4340 3040,4290 2860,4290 2800,4230 2800,4201.57
NetD4_1 on Bottom Layer "Bottom Layer-No Net 8" (solid, remove dead copper, pour order 25): 3465,4590 3465,4675 3410,4730 3285,4730 3250,4765 3190,4765 3185,4765 3180,4765 3180,4835 3400,4835 3535,4700 3535,4590 3465,4590
PWR_GND on Bottom Layer "Bottom Layer-No Net 10" (solid, remove dead copper, pour order 36): 2905,4185 2905,4180 3050,4035 3050,3875 3100,3825 3780,3825 3825,3870 3825,4050 3735,4140 3650,4140 3620,4110 3620,4065 3650,4035 3705,4035 3760,3980 3760,3900 3735,3875 3620,3875 3580,3915 3550,3915 3195,3915 3180,3930 3180,4100 3180,4110 3190,4120 3190,4200 3175,4215 2935,4215 2905,4185
IO_GND on Top Layer "IO_GND_L01_P042" (solid, remove dead copper, pour order 42): 200,2700 2000,2700 2000,400 200,400 200,2700
GND on Top Layer "Top Layer-No Net" (solid, remove dead copper, pour order 22): 2200,2700 2200,400 3600,400 3600,685.21 cw(c3614.79,685.21) 3614.79,700 4400,700 4400,400 7800,400 7800,2700 2200,2700

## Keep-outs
Keep-Out Layer:
  text ".Layer_Name" at 578,-857.99 h60

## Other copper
Top Layer:
  text ".Layer_Name" at 578,-857.99 h60
Bottom Layer:
  text ".Layer_Name" at 578,-857.99 h60

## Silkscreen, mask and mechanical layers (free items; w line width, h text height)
Top Overlay:
  lines w7: 5200,3880 5200,4125 ; 5950,3950 5950,4125
  lines w7.87: 150,900 200,900 ; 170,870 200,900 ; 170,930 200,900 ; 180,1070 150,1100 ; 180,1130 150,1100 ; 200,1100 150,1100 ; 3245,1250 3295,1250 ; 3265,1220 3295,1250 ; 3265,1280 3295,1250 ; 3275,1320 3245,1350 ; 3275,1380 3245,1350 ; 3295,1350 3245,1350
  lines w10: 2100,1150 2100,1203.54 ; 2100,1396.45 2100,1450 ; 5950,3250 5950,3450 ; 6062.5,3450 6062.5,3850 ; 5950,3450 5950,3850 6175,3850 6175,3450 5950,3450
  lines w20: 100,600 200,600 200,400 2000,400 2000,1150 2200,1150 2200,400 3600,400 3600,700 4400,700 4400,400 7800,400 7800,2700 5529,2700 5529,2800 5529,2900 7800,2900 7800,5400 4400,5400 4400,5100 3600,5100 3600,5400 200,5400 200,4600 100,4600 ; 100,1400 200,1400 200,2700 2000,2700 2000,1450 2200,1450 2200,2700 5329,2700 5329,2900 200,2900 200,3900.45 199.55,3900 100,3900
  text "UNIVERSAL AC TO 12VDC DOMAIN" at 250,5300 h80
  text "N" at 100,4390 h200
  text "-" at 5137,4285 h100 r270
  text "-" at 5882.43,4285 h100 r270
  text "+" at 5130,4194 h100 r270
  text "+" at 5875.43,4194 h100 r270
  text "12VDC POWER" at 6562.99,4113.19 h80
  text "12VDC" at 5235,4020 h80
  text "12VDC OUT" at 5980,4020 h80
  text "L" at 100,3990 h200
  text "PRE CHOKE" at 5235,3950 h80
  text "0.5A / 6W MAX" at 5980,3950 h80
  text "MONITOR ONLY" at 5235,3880 h80
  text "90VAC - 265VAC IN" at 340,3680 h80
  text "+" at 6024,3434.57 h100 r180
  text "-" at 6140,3425 h100 r180
  text "DOMAIN BRIDGE" at 5975,3320 h80
  text "REMOVE TO DISCONNECT CSM_VCC DOMAIN" at 5975,3250 h80
  text "IO DOMAIN" at 245,2600 h80
  text "CSM_VCC (3.3VDC) DOMAIN" at 2240,2600 h80
  text "+" at 4520,2471 h100 r90
  text "3.3VDC OUT" at 3755,2450.96 h80
  text "0.1A / 0.3W MAX" at 3755,2380.96 h80
  text "-" at 4513,2380 h100 r90
  text "DNP" at 4515,2265 h40
  text "CSM Port" at 2910,1450 h100
  text "VCC" at 2800,1330 h80
  text "To CSM TX" at 3320,1325 h80
  text "IO VCC" at 30,1270 h80
  text "GND" at 2800,1230 h80
  text "To CSM RX" at 3320,1225 h80
  text "IO" at 40,1070 h80
  text "IO" at 40,870 h80
  text "IO GND" at 40,680 h80
  text "IO POWER" at 1520,450 h80
  text "CSM POWER" at 2280,450 h80
  text "TIDM-CAPTOUCHEMCREF" at 665,115 h100
  text "PSM UAC to 3.3VDC" at 1910,115 h100
  text ".Layer_Name" at 578,-857.99 h60
Bottom Overlay:
  text ".Layer_Name" at 578,-857.99 h60
Top Paste:
  text ".Layer_Name" at 578,-857.99 h60
Bottom Paste:
  text ".Layer_Name" at 578,-857.99 h60
Top Solder:
  text ".Layer_Name" at 578,-857.99 h60
  text ".Layer_Name" at 578,-857.99 h60
Bottom Solder:
  text ".Layer_Name" at 578,-857.99 h60
Drill Guide:
  text ".Layer_Name" at 578,-857.99 h60
M1 Board Outline:
  lines w19.68: 0,0 0,5800 3800,5800 3800,5300 4000,5300 4200,5300 4200,5800 8000,5800 8000,0 4200,0 4200,500 4000,500 3800,500 3800,0 0,0
  text ".Layer_Name" at 578,-857.99 h60
M2 Board Dimensions:
  rectangle: 125,-400 500,-275
  rectangle: 0,-275 125,-150
  lines w7: 0,-275 1000,-275 ; 125,-400 125,-150 ; 250,-400 250,-150 ; 500,-400 500,-150 ; 750,-400 750,-150 ; 0,-400 0,-150 1000,-150 1000,-400 0,-400
  text ".Layer_Name" at 578,-857.99 h60
M3 3D STEP Top:
  text ".Layer_Name" at 578,-857.99 h60
M4 3D STEP Bottom:
  text ".Layer_Name" at 578,-857.99 h60
M5 Assembly Top:
  lines w10: -291,-523 -291,-1133 3714,-1133 ; 1285,-1133 -290.5,-1133 -290.5,-523 ; 2174,-1133 2174,-523 ; 3441,-726.33 3441,-523 ; 4281,-726.33 4281,-523 ; 4903,-1139.5 4903,-936.67 ; -290.5,-523 6311,-523 ; -290.5,-523 6311,-523 ; 3714,-1133 6311,-1133 ; 3714,-1133 6311,-1133 ; 6311,-1133 6311,-523 ; 6311,-1133 6311,-523 ; -291,-929.67 6309,-929.67 -291,-929.67 ; -291,-726.33 6311,-726.33 -291,-726.33
  text "PCB VIEWED FROM TOP SIDE" at -227.5,-655.17 h60
  text "BOARD #:" at 2249,-655.17 h60
  text ".PRJ_Number" at 2794.5,-655.17 h60
  text "REV:" at 3639,-655.17 h60
  text ".PCB_Rev" at 3930.5,-655.17 h60
  text "SVN REV:" at 4477,-655.17 h60
  text "TID #:" at 2249,-858.5 h60
  text ".TID" at 2794.5,-858.5 h60
  text "PLOT NAME =" at -227.5,-1063.84 h60
  text ".plot_File_Name" at 578,-1063.84 h60
  text "GENERATED    :" at 2251,-1063.84 h60
  text ".Print_Date" at 3120.5,-1063.84 h60
  text ".Print_Time" at 3849.5,-1063.84 h60
  text "TEXAS INSTRUMENTS" at 5114,-1063.84 h60
M6 Assembly Bottom:
  lines w10: 1116.5,-1140 1116.5,-937.17 ; 1738.5,-726.83 1738.5,-523.5 ; 2578.5,-726.83 2578.5,-523.5 ; 3845.5,-1133.5 3845.5,-523.5 ; -291.5,-523.5 6310,-523.5 ; -291.5,-523.5 -291.5,-1133.5 2305.5,-1133.5 ; -291.5,-523.5 6310,-523.5 ; 2305.5,-1133.5 6310.5,-1133.5 ; 2305.5,-1133.5 6310.5,-1133.5 ; 6310,-1133.5 6310,-523.5 ; 6310,-1133.5 4734.5,-1133.5 6310,-1133.5 ; 6310,-1133.5 6310,-523.5 ; 6310.5,-1133.5 6310.5,-523.5 6310.5,-1133.5 ; -291.5,-726.83 6310.5,-726.83 -291.5,-726.83 ; -289.5,-930.17 6310.5,-930.17 -289.5,-930.17
  text ".VersionControl_RevNumber" at 1036.5,-655.67 h60
  text "SVN REV:" at 1542.5,-655.67 h60
  text ".PCB_Rev" at 2089,-655.67 h60
  text "REV:" at 2380.5,-655.67 h60
  text ".PRJ_Number" at 3225,-655.67 h60
  text "BOARD #:" at 3770.5,-655.67 h60
  text "PCB VIEWED FROM BOTTOM SIDE" at 6247,-655.67 h60
  text ".TID" at 3225,-859 h60
  text "TID #:" at 3770.5,-859 h60
  text "TEXAS INSTRUMENTS" at 905.5,-1064.34 h60
  text ".Print_Time" at 2170,-1064.34 h60
  text ".Print_Date" at 2899,-1064.34 h60
  text "GENERATED    :" at 3768.5,-1064.34 h60
  text ".plot_File_Name" at 5441.5,-1064.34 h60
  text "PLOT NAME =" at 6247,-1064.34 h60
M9 Title Sheet:
  drawing of 58 lines, arcs and shapes, not listed
  text "1" at 739.84,8036.5 h70
  text "2" at 3235.5,8036.5 h70
  text "3" at 5724.84,8036.5 h70
  text "4" at 8231.51,8036.5 h70
  text "5" at 10730.5,8036.5 h70
  text "6" at 13235.5,8036.5 h70
  text "A" at -416.5,6893.5 h70
  text "A" at 14383.5,6893.5 h70
  text "B" at -416.5,4513.5 h70
  text "B" at 14383.5,4513.5 h70
  text "C" at -416.5,2138.5 h70
  text "C" at 14383.5,2138.5 h70
  text "PROJECT TITLE:" at 11343.5,277.5 h45
  text "TIDM-CAPTOUCHEMCREF PSM 12V to 3.3V" at 11393.5,144.17 h70
  text "DESIGNED FOR:" at 11343.5,-23.5 h45
  text "TI Designs" at 11393.5,-163.5 h70
  text "D" at -416.5,-231.5 h70
  text "D" at 14383.5,-231.5 h70
  text "FILE NAME:" at 11343.5,-323.5 h45
  text ".PCB_File_Name_No_Path" at 11393.5,-443.5 h70
  text "Texas Instruments (TI) and/or its licensors do not warrant the accuracy or completeness of this specification" at 6374,-605.34 h45
  text "ENGINEER:" at 11343.5,-613.5 h45
  text "LAYOUT BY:" at 12848.5,-613.5 h45
  text "or any information contained therein. TI and/or its licensors do not warrant that this design will meet" at 6329.01,-718 h45
  text "W. Schnoor" at 11393.5,-768.49 h70
  text "W. Schnoor" at 12899,-768.49 h70
  text "the specifications, will be suitable for your application or fit for any particular purpose, or will operate in" at 6329.01,-830.67 h45
  text ".Layer_Name" at 578,-857.99 h60
  text "ALTIUM DESIGNER VERSION:" at 12848.5,-923.5 h45
  text "an implementation. TI and/or its licensors do not warrant that the design is production worthy. You should" at 6329.01,-943.33 h45
  text "completely validate and test your design implementation to confirm the system functionality for your application." at 6374,-1056 h45
  text ".print_Scale" at 11393.5,-1056.83 h70
  text ".Application_BuildNumber" at 12899,-1056.83 h70
  text "1" at 739.84,-1263.5 h70
  text "2" at 3235.5,-1263.5 h70
  text "3" at 5724.84,-1263.5 h70
  text "4" at 8231.51,-1263.5 h70
  text "5" at 10730.5,-1263.5 h70
  text "6" at 13235.5,-1263.5 h70
M10 Fab Notes:
  drawing of 185 lines, arcs and shapes, not listed
  text "DESIGN INFORMATION" at 12381.02,5910 h60
  text "MIN. TRACK WIDTH:" at 11736.46,5730 h60
  text "8" at 12832.7,5730 h60
  text "MIL" at 12987.46,5730 h60
  text "MIN. CLEARANCE:" at 11736.46,5598 h60
  text "0.2" at 12772.7,5598 h60
  text "mm" at 12987.46,5598 h60
  text "MIN. VIA PAD SIZE:" at 11736.46,5466 h60
  text "24" at 12802.71,5466 h60
  text "MIL" at 12987.46,5466 h60
  text "0.05mm (2MIL)" at 12431.46,5324.29 h60
  text "MINIMUM ANNULAR RING" at 11407.23,5320 h60
  text "EXTERNAL" at 13139.46,5320 h60
  text "PER" at 11607.23,5202 h60
  text "IPC-D-275 CLASS 2 LEVEL C" at 11827.23,5202 h60
  text "MIL, HOLES" at 13315.46,5089.71 h60
  text "+/-" at 12923,5089 h60
  text "+/-" at 13777,5089 h60
  text "REGISTRATION TOLERANCES:" at 11407.23,5084 h60
  text "METAL" at 12607,5084 h60
  text "5" at 13183.2,5084 h60
  text "3" at 14016.2,5084 h60
  text "MIL" at 14132.46,5084 h60
  text "MATERIAL:" at 11332.46,4874.54 h60
  text "FR-4 High Tg" at 12318.9,4734.21 h60
  text "FR-408" at 11753.46,4725.64 h60
  text "X" at 12165.46,4725.64 h60
  text "OTHER" at 13241.46,4725.64 h60
  text "62 MIL (1.6mm) +/-10%" at 12073.56,4562.92 h60
  text "THICKNESS:" at 11407.23,4558.64 h60
  text "X" at 11945.4,4558.64 h60
  text "OTHER" at 13358.46,4558.64 h60
  text "TOLERANCE:" at 11407.23,4400.64 h60
  text "X" at 12246.53,4400.64 h60
  text "ANSI IPC-6012 TYPE 3 CLASS 2" at 12433.48,4400.64 h60
  text "OTHER +/-" at 12433.46,4244.64 h60
  text "BOW & TWIST:" at 11407.23,4087.64 h60
  text "X" at 12246.53,4087.64 h60
  text "ANSI IPC-6012 TYPE 3 CLASS 2" at 12433.48,4087.64 h60
  text "OTHER +/-" at 12433.46,3929.13 h60
  text "DRILLING:" at 11332.46,3790.64 h60
  text "REFERENCE:" at 11407.23,3673.64 h60
  text "X" at 12055.46,3673.64 h60
  text "AS SHOWN" at 12242.46,3673.64 h60
  text "X" at 12956.46,3673.64 h60
  text "NC_DRILL FILES" at 13093.46,3673.64 h60
  text "PTH MIN COPPER THICKNESS:" at 11407.23,3515.64 h60
  text "X" at 12757.46,3515.64 h60
  text "1MIL" at 12894.46,3515.64 h60
  text "OTHER" at 13391.46,3515.64 h60
  text "BOARD FINISH:" at 11332.46,3356.64 h60
  text "SILKSCREEN:" at 11487.68,3238.64 h60
  text "X" at 12436.46,3238.64 h60
  text "TOP" at 12562.46,3238.64 h60
  text "X" at 12946.46,3238.64 h60
  text "BOTTOM" at 13073.46,3238.64 h60
  text "SILKSCREEN COLOR:" at 11487.68,3071.64 h60
  text "X" at 12435.42,3071.64 h60
  text "WHITE" at 12562.46,3071.64 h60
  text "OTHER" at 13073.46,3071.64 h60
  text "SOLDER RESIST COLOR:" at 11487.68,2901.64 h60
  text "X" at 12055.42,2742.44 h60
  text "GREEN" at 12182.46,2742.44 h60
  text "BLUE" at 12773.46,2742.44 h60
  text "OTHER" at 13311.46,2742.44 h60
  text "IMMERSION GOLD (ENIG)" at 12393.46,2553.92 h60
  text "ENEPIG" at 13731,2550.64 h60
  text "SURFACE FINISH:" at 11332.46,2549.64 h60
  text "X" at 12206.51,2549.64 h60
  text "IMM. TIN/SILVER OR EQUIV" at 11662,2392.64 h60
  text "OTHER" at 13093.46,2392.64 h60
  text "ARRAY/PANEL:" at 11332.46,2213.64 h60
  text "CUT AND TRIM PER MECH LAYER 1" at 12393.46,2209.35 h60
  text "N.C. ROUTE" at 12393.46,2057.64 h60
  text "X" at 13072.46,2057.64 h60
  text "V. SCORE" at 13259.46,2057.64 h60
  text "CERTIFICATION:" at 11332.46,1920.64 h60
  text "MATERIALS AND WORKMANSHIP FOR ALL PCBS" at 12057.46,1920.64 h60
  text "TO MEET OR EXCEED THE REQUIREMENTS OF:" at 12057.46,1822.64 h60
  text "X" at 11683.96,1686.13 h60
  text "ANSI IPC-A-600F CLASS ->" at 11822.96,1686.13 h60
  text "X" at 13462.02,1686.13 h60
  text "2" at 13580.96,1686.14 h60
  text "1" at 13265.96,1684.64 h60
  text "3" at 13934.96,1684.64 h60
  text "X" at 11686.02,1526.64 h60
  text "UL 94V-0" at 11822.96,1526.64 h60
  text "X" at 12498.02,1526.64 h60
  text "RoHS" at 12634.96,1526.64 h60
  text "OTHER" at 13279.36,1526.64 h60
  text "PER ORDER" at 13676.42,1526.64 h60
  text "ADDITIONAL REQUIREMENTS:" at 11332.46,1385.64 h60
  text "MICROSECTION:" at 11407.23,1270.64 h60
  text "YES" at 12312.96,1270.64 h60
  text "REQUIRED" at 13174.46,1114.49 h60
  text "BARE BOARD ELEC. TEST:" at 11407.23,1111.64 h60
  text "NONE" at 12712.96,1111.64 h60
  text "X" at 13047.46,1111.64 h60
  text "PER ORDER" at 13766.46,1111.64 h60
  text "MANUFACTURER'S UL:" at 11407.23,954.64 h60
  text "RAIL" at 12572.96,950.35 h60
  text "METAL" at 13064.77,950.35 h60
  text "X" at 13440,950 h60
  text "SILK" at 13576.46,950.35 h60
  text ".Layer_Name" at 578,-857.99 h60
M11 Gerber Information:
  lines w10: -291,-523 -291,-1133 3714,-1133 ; 1285,-1133 -290.5,-1133 -290.5,-523 ; 2174,-1133 2174,-523 ; 3441,-726.33 3441,-523 ; 4281,-726.33 4281,-523 ; 4903,-1139.5 4903,-936.67 ; -290.5,-523 6311,-523 ; -290.5,-523 6311,-523 ; 3714,-1133 6311,-1133 ; 3714,-1133 6311,-1133 ; 6311,-1133 6311,-523 ; 6311,-1133 6311,-523 ; -291,-929.67 6309,-929.67 -291,-929.67 ; -291,-726.33 6311,-726.33 -291,-726.33
  text "ALL ARTWORK VIEWED FROM TOP SIDE" at -227.5,-655.17 h60
  text "BOARD #:" at 2249,-655.17 h60
  text ".PRJ_Number" at 2794.5,-655.17 h60
  text "REV:" at 3639,-655.17 h60
  text ".PCB_Rev" at 3930.5,-655.17 h60
  text "SVN REV:" at 4477,-655.17 h60
  text "LAYER NAME =" at -227.5,-857.99 h60
  text "TID #:" at 2249,-858.5 h60
  text ".TID" at 2794.5,-858.5 h60
  text "PLOT NAME =" at -227.5,-1063.84 h60
  text ".plot_File_Name" at 578,-1063.84 h60
  text "GENERATED    :" at 2251,-1063.84 h60
  text ".Print_Date" at 3120.5,-1063.84 h60
  text ".Print_Time" at 3849.5,-1063.84 h60
  text "TEXAS INSTRUMENTS" at 5114,-1063.84 h60
M12 Stackup:
  drawing of 191 lines, arcs and shapes, not listed
  text "Layer" at 9790.34,7830 h60
  text "Name" at 10200.26,7830 h60
  text "Material" at 11130,7830 h60
  text "Thickness" at 11989.77,7830 h60
  text "Constant" at 12639.6,7830 h60
  text "Board Layer Stack" at 13209.46,7830 h60
  text "1" at 9790.34,7710 h60
  text "Top Overlay" at 10200.26,7710 h60
  text "2" at 9790.34,7590 h60
  text "Top Solder" at 10200.26,7590 h60
  text "Solder Resist" at 11130,7590 h60
  text "0.40mil" at 11989.77,7590 h60
  text "3.5" at 12639.6,7590 h60
  text "3" at 9790.34,7470 h60
  text "Top Layer" at 10200.26,7470 h60
  text "Copper" at 11130,7470 h60
  text "1.40mil" at 11989.77,7470 h60
  text "4" at 9790.34,7350 h60
  text "Dielectric1" at 10200.26,7350 h60
  text "FR-4" at 11130,7350 h60
  text "59.20mil" at 11989.77,7350 h60
  text "4.8" at 12639.6,7350 h60
  text "5" at 9790.34,7230 h60
  text "Bottom Layer" at 10200.26,7230 h60
  text "Copper" at 11130,7230 h60
  text "1.40mil" at 11989.77,7230 h60
  text "6" at 9790.34,7110 h60
  text "Bottom Solder" at 10200.26,7110 h60
  text "Solder Resist" at 11130,7110 h60
  text "0.40mil" at 11989.77,7110 h60
  text "3.5" at 12639.6,7110 h60
  text "7" at 9790.34,6990 h60
  text "Bottom Overlay" at 10200.26,6990 h60
  text ".Layer_Name" at 578,-857.99 h60
M13 Component Bodies Top:
  text ".Layer_Name" at 578,-857.99 h60
M14 Component Bodies Bottom:
  text ".Layer_Name" at 578,-857.99 h60
M15 Courtyards Top:
  text ".Layer_Name" at 578,-857.99 h60
M16 Courtyards Bottom:
  text ".Layer_Name" at 578,-857.99 h60
Drill Drawing:
  text ".Layer_Name" at 578,-857.99 h60

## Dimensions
0,-400 to 1000,-400 on M2 Board Dimensions
0,5800 to 8000,5800 on M2 Board Dimensions
8000,5800 to 8000,0 on M2 Board Dimensions
4000,5300 to 0,5800 on M2 Board Dimensions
